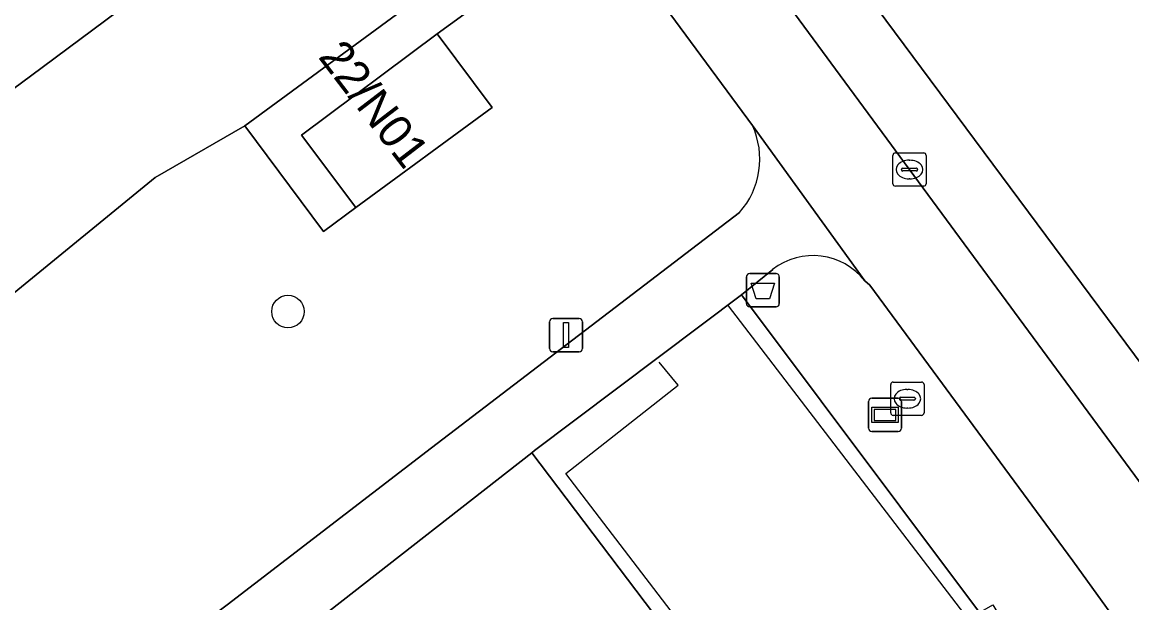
# Model space of a CAD drawing. Extents: x 163426 to 164192, y 380329 to 381641.
# Drawn here: x 163863.26 to 163896.61, y 381091.39 to 381108.84 of the extents above; entities that cross this region are included whole.
import ezdxf

# ---------------------------------------------------------------- set-up
doc = ezdxf.new("R2010")
doc.units = 0
for name, color, linetype in [('IMGEO_Afvalbak', 7, 'Continuous'), ('IMGEO_Boom', 7, 'Continuous'), ('IMGEO_Brandkraan', 7, 'Continuous'), ('IMGEO_Erf', 7, 'Continuous'), ('IMGEO_Fietspad_open', 7, 'Continuous'), ('IMGEO_Groenvoorziening', 7, 'Continuous'), ('IMGEO_Hek', 7, 'Continuous'), ('IMGEO_Kolk', 7, 'Continuous'), ('IMGEO_Lichtmast', 7, 'Continuous'), ('IMGEO_Pand', 7, 'Continuous'), ('IMGEO_Pand_nummerreeks', 7, 'Continuous'), ('IMGEO_Verklikker', 7, 'Continuous'), ('IMGEO_Voetpad_halfverhard', 7, 'Continuous'), ('IMGEO_Voetpad_open', 7, 'Continuous')]:
    doc.layers.add(name, color=color, linetype=linetype)

msp = doc.modelspace()

# ---------------------------------------------------------------- linework, layer by layer
at = {"layer": 'IMGEO_Afvalbak'}
for p, q in [((163885.023, 381100.383), (163885.023, 381101.183)), ((163885.023, 381101.183), (163885.023, 381100.383)), ((163885.123, 381101.283), (163885.913, 381101.283)), ((163885.913, 381101.283), (163885.123, 381101.283)), ((163886.013, 381101.183), (163886.013, 381100.383)), ((163886.013, 381100.383), (163886.013, 381101.183)), ((163885.913, 381100.283), (163885.123, 381100.283)), ((163885.123, 381100.283), (163885.913, 381100.283))]:
    msp.add_line(p, q, dxfattribs=at)
msp.add_lwpolyline([(163885.166, 381100.997), (163885.87, 381100.997), (163885.721, 381100.527), (163885.315, 381100.527), (163885.166, 381100.997)], dxfattribs=at)
for centre, start, end in [((163885.123, 381101.183), 90, 180), ((163885.123, 381101.183), 90, 180), ((163885.913, 381101.183), 0, 90), ((163885.913, 381101.183), 360, 90), ((163885.123, 381100.383), 180, 270), ((163885.123, 381100.383), 180, 270), ((163885.913, 381100.383), 270, 0), ((163885.913, 381100.383), 270, 0)]:
    msp.add_arc(centre, 0.1, start, end, dxfattribs=at)
at = {"layer": 'IMGEO_Boom'}
msp.add_circle((163871.246, 381100.142), 0.489, dxfattribs=at)
at = {"layer": 'IMGEO_Brandkraan'}
for p, q in [((163889.361, 381097.097), (163889.361, 381097.949)), ((163889.436, 381098.023), (163890.288, 381098.023)), ((163889.849, 381097.803), (163889.874, 381097.803)), ((163890.362, 381097.949), (163890.362, 381097.097)), ((163889.62, 381097.517), (163889.62, 381097.529)), ((163890.058, 381097.48), (163889.66, 381097.48)), ((163889.663, 381097.566), (163890.061, 381097.566)), ((163890.104, 381097.529), (163890.104, 381097.517)), ((163889.872, 381097.243), (163889.847, 381097.243)), ((163890.288, 381097.023), (163889.436, 381097.023))]:
    msp.add_line(p, q, dxfattribs=at)
for points in [[(163889.361, 381097.097), (163889.361, 381097.949)], [(163889.436, 381098.023), (163890.288, 381098.023)], [(163890.362, 381097.949), (163890.362, 381097.097)], [(163890.288, 381097.023), (163889.436, 381097.023)]]:
    msp.add_lwpolyline(points, dxfattribs=at)
for centre, radius, start, end in [((163889.438, 381097.947), 0.0765, 91.552, 178.448), ((163889.438, 381097.947), 0.0765, 91.552, 178.448), ((163890.286, 381097.947), 0.0765, 1.552, 88.448), ((163890.286, 381097.947), 0.0765, 1.552, 88.448), ((163889.66, 381097.526), 0.0403, 85.8775, 175.7526), ((163889.657, 381097.516), 0.0366, 178.938, 274.7102), ((163890.061, 381097.523), 0.043, 264.8664, 352.4533), ((163890.065, 381097.528), 0.0386, 1.7309, 96.639), ((163889.438, 381097.099), 0.0765, 181.552, 268.448), ((163889.438, 381097.099), 0.0765, 181.552, 268.448), ((163890.286, 381097.099), 0.0765, 271.552, 358.448), ((163890.286, 381097.099), 0.0765, 271.552, 358.448)]:
    msp.add_arc(centre, radius, start, end, dxfattribs=at)
for centre, major_axis, ratio, start_param, end_param in [((163889.848, 381097.523), (-0.387, 0.002), 0.722429, 4.712389, 7.853982), ((163889.873, 381097.523), (-0.39, 0.002), 0.717154, 1.570796, 4.712389)]:
    msp.add_ellipse(centre, major_axis=major_axis, ratio=ratio, start_param=start_param, end_param=end_param, dxfattribs=at)
at = {"layer": 'IMGEO_Erf'}
msp.add_lwpolyline([(163882.295, 381118.226), (163898.019, 381097.05), (163899.274, 381095.308), (163900.905, 381096.518), (163902.973, 381093.731), (163901.342, 381092.521), (163917.592, 381070.453), (163952.531, 381076.448), (163942.036, 381199.692)], dxfattribs=at)
at = {"layer": 'IMGEO_Fietspad_open'}
for points in [[(163920.063, 381063.521), (163916.003, 381069.011), (163879.294, 381118.846)], [(163878.091, 381115.406), (163879.855, 381113.008), (163880.581, 381112.021), (163885.203, 381105.739), (163888.584, 381101.063), (163888.737, 381100.935), (163894.831, 381092.652), (163895.849, 381091.249), (163896.67, 381090.133), (163898.402, 381087.778), (163898.929, 381087.061), (163907.808, 381074.986), (163908.685, 381073.793), (163913.644, 381067.049), (163914.985, 381065.235), (163917.772, 381061.459), (163917.806, 381061.505)]]:
    msp.add_lwpolyline(points, dxfattribs=at)
at = {"layer": 'IMGEO_Groenvoorziening'}
for points in [[(163875.27, 381115.855), (163874.338, 381115.123), (163867.872, 381110.455), (163866.166, 381109.192), (163863.855, 381107.48), (163861.136, 381105.466), (163848.379, 381095.943), (163850.493, 381094.839), (163851.753, 381095.363), (163853.983, 381093.322), (163867.256, 381104.176)], [(163867.256, 381104.176), (163869.951, 381105.722), (163879.855, 381113.008), (163878.091, 381115.406)], [(163885.203, 381105.739), (163880.581, 381112.021), (163875.725, 381108.486), (163877.378, 381106.277), (163873.284, 381103.268), (163872.309, 381102.549), (163869.951, 381105.722), (163867.256, 381104.176), (163853.983, 381093.322), (163851.753, 381095.363), (163850.493, 381094.839), (163848.379, 381095.943), (163844.187, 381092.814), (163844.683, 381091.092)], [(163860.665, 381084.431), (163863.932, 381087.182), (163869.42, 381091.331), (163875.557, 381096.043), (163881.424, 381100.523), (163884.816, 381103.12)], [(163885.813, 381101.41), (163884.881, 381100.649), (163892.032, 381091.103), (163892.433, 381091.325), (163893.363, 381089.769), (163893.712, 381086.589), (163885.188, 381079.149), (163877.401, 381069.894), (163877.35, 381068.327), (163876.539, 381066.473), (163872.253, 381063.156), (163871.244, 381061.59), (163871.684, 381058.886), (163871, 381056.23), (163869.868, 381054.37), (163867.112, 381051.126), (163865.984, 381046.133)], [(163873.767, 381061.119), (163873.306, 381061.714), (163874.824, 381062.84), (163881.373, 381067.697), (163879.447, 381070.311), (163879.387, 381070.393), (163879.593, 381070.547), (163883.835, 381073.718), (163883.575, 381074.205), (163883.054, 381074.889), (163887.858, 381079.918), (163898.402, 381087.778), (163896.67, 381090.133), (163895.849, 381091.249), (163894.831, 381092.652), (163888.737, 381100.935), (163888.584, 381101.063)], [(163859.052, 381037.328), (163858.039, 381032.201), (163856.309, 381029.254), (163852.062, 381030.665), (163857.097, 381046.206), (163865.555, 381060.95), (163867.201, 381064.226), (163858.767, 381069.713), (163869.611, 381086.378), (163878.149, 381080.823), (163885.102, 381087.269), (163878.573, 381095.902), (163872.498, 381091.145), (163864.015, 381084.713)]]:
    msp.add_lwpolyline(points, dxfattribs=at)
msp.add_lwpolyline([(163884.881, 381100.649), (163878.655, 381095.966), (163878.573, 381095.902), (163885.102, 381087.269), (163885.54, 381087.511), (163891.682, 381090.91), (163892.032, 381091.103)], close=True, dxfattribs=at)
for centre, radius, start, end in [((163883.009, 381104.725), 2.417, 318.3836, 24.8053), ((163887.024, 381099.846), 1.978, 37.9623, 127.7622)]:
    msp.add_arc(centre, radius, start, end, dxfattribs=at)
at = {"layer": 'IMGEO_Hek'}
for points in [[(163884.476, 381100.317), (163891.682, 381090.91)], [(163885.54, 381087.511), (163879.594, 381095.281), (163882.973, 381097.928), (163882.403, 381098.624)]]:
    msp.add_lwpolyline(points, dxfattribs=at)
at = {"layer": 'IMGEO_Kolk'}
for p, q in [((163889.425, 381103.985), (163889.425, 381104.837)), ((163889.5, 381104.911), (163890.352, 381104.911)), ((163890.426, 381104.837), (163890.426, 381103.985)), ((163889.727, 381104.454), (163890.125, 381104.454)), ((163889.913, 381104.691), (163889.938, 381104.691)), ((163889.684, 381104.405), (163889.684, 381104.417)), ((163890.122, 381104.368), (163889.724, 381104.368)), ((163889.936, 381104.131), (163889.911, 381104.131)), ((163890.168, 381104.417), (163890.168, 381104.405)), ((163890.352, 381103.911), (163889.5, 381103.911))]:
    msp.add_line(p, q, dxfattribs=at)
for points in [[(163889.425, 381103.985), (163889.425, 381104.837)], [(163889.5, 381104.911), (163890.352, 381104.911)], [(163890.426, 381104.837), (163890.426, 381103.985)], [(163890.352, 381103.911), (163889.5, 381103.911)]]:
    msp.add_lwpolyline(points, dxfattribs=at)
for centre, radius, start, end in [((163889.502, 381104.835), 0.0765, 91.552, 178.448), ((163889.502, 381104.835), 0.0765, 91.552, 178.448), ((163890.35, 381104.835), 0.0765, 1.552, 88.448), ((163890.35, 381104.835), 0.0765, 1.552, 88.448), ((163889.724, 381104.414), 0.0403, 85.8775, 175.7526), ((163890.129, 381104.416), 0.0386, 1.7309, 96.639), ((163889.721, 381104.404), 0.0366, 178.938, 274.7102), ((163890.125, 381104.411), 0.043, 264.8664, 352.4533), ((163889.502, 381103.987), 0.0765, 181.552, 268.448), ((163889.502, 381103.987), 0.0765, 181.552, 268.448), ((163890.35, 381103.987), 0.0765, 271.552, 358.448), ((163890.35, 381103.987), 0.0765, 271.552, 358.448)]:
    msp.add_arc(centre, radius, start, end, dxfattribs=at)
for centre, major_axis, ratio, start_param, end_param in [((163889.912, 381104.411), (-0.387, 0.002), 0.722429, 4.712389, 7.853982), ((163889.937, 381104.411), (-0.39, 0.002), 0.717154, 1.570796, 4.712389)]:
    msp.add_ellipse(centre, major_axis=major_axis, ratio=ratio, start_param=start_param, end_param=end_param, dxfattribs=at)
at = {"layer": 'IMGEO_Lichtmast'}
for p, q in [((163879.105, 381099.036), (163879.105, 381099.836)), ((163879.105, 381099.836), (163879.105, 381099.036)), ((163879.205, 381099.936), (163879.995, 381099.936)), ((163879.995, 381099.936), (163879.205, 381099.936)), ((163880.095, 381099.836), (163880.095, 381099.036)), ((163880.095, 381099.036), (163880.095, 381099.836)), ((163879.995, 381098.936), (163879.205, 381098.936)), ((163879.205, 381098.936), (163879.995, 381098.936))]:
    msp.add_line(p, q, dxfattribs=at)
msp.add_lwpolyline([(163879.525, 381099.811), (163879.675, 381099.811), (163879.675, 381099.061), (163879.525, 381099.061), (163879.525, 381099.811)], dxfattribs=at)
for centre, start, end in [((163879.205, 381099.836), 90, 180), ((163879.205, 381099.836), 90, 180), ((163879.995, 381099.836), 0, 90), ((163879.995, 381099.836), 360, 90), ((163879.205, 381099.036), 180, 270), ((163879.205, 381099.036), 180, 270), ((163879.995, 381099.036), 270, 0), ((163879.995, 381099.036), 270, 0)]:
    msp.add_arc(centre, 0.1, start, end, dxfattribs=at)
at = {"layer": 'IMGEO_Pand'}
for points in [[(163865.949, 381113.043), (163869.523, 381115.699), (163868.22, 381117.481), (163868.755, 381117.872), (163866.401, 381121.058), (163857.795, 381114.702), (163859.858, 381111.91), (163857.605, 381110.245), (163861.136, 381105.466), (163863.855, 381107.48), (163866.166, 381109.192), (163864.245, 381111.777)], [(163873.284, 381103.268), (163877.378, 381106.277), (163875.725, 381108.486), (163871.655, 381105.448)]]:
    msp.add_lwpolyline(points, close=True, dxfattribs=at)
at = {"layer": 'IMGEO_Verklikker'}
for p, q in [((163888.794, 381097.537), (163889.584, 381097.537)), ((163889.584, 381097.537), (163888.794, 381097.537)), ((163888.694, 381096.637), (163888.694, 381097.437)), ((163888.694, 381097.437), (163888.694, 381096.637)), ((163889.684, 381097.437), (163889.684, 381096.637)), ((163889.684, 381096.637), (163889.684, 381097.437)), ((163889.584, 381096.537), (163888.794, 381096.537)), ((163888.794, 381096.537), (163889.584, 381096.537))]:
    msp.add_line(p, q, dxfattribs=at)
for points in [[(163888.795, 381097.269), (163889.583, 381097.269), (163889.583, 381096.805), (163888.795, 381096.805), (163888.795, 381097.269)], [(163888.86, 381097.204), (163888.86, 381096.87), (163889.518, 381096.87), (163889.518, 381097.204), (163888.86, 381097.204)]]:
    msp.add_lwpolyline(points, dxfattribs=at)
for centre, start, end in [((163888.794, 381097.437), 90, 180), ((163888.794, 381097.437), 90, 180), ((163889.584, 381097.437), 0, 90), ((163889.584, 381097.437), 360, 90), ((163888.794, 381096.637), 180, 270), ((163888.794, 381096.637), 180, 270), ((163889.584, 381096.637), 270, 0), ((163889.584, 381096.637), 270, 0)]:
    msp.add_arc(centre, 0.1, start, end, dxfattribs=at)
at = {"layer": 'IMGEO_Voetpad_halfverhard'}
for points in [[(163888.584, 381101.063), (163885.203, 381105.739)], [(163884.816, 381103.12), (163881.424, 381100.523), (163875.557, 381096.043), (163869.42, 381091.331), (163863.932, 381087.182), (163860.665, 381084.431)], [(163864.015, 381084.713), (163872.498, 381091.145), (163878.573, 381095.902), (163878.655, 381095.966), (163884.881, 381100.649), (163885.813, 381101.41)]]:
    msp.add_lwpolyline(points, dxfattribs=at)
for centre, radius, start, end in [((163883.009, 381104.725), 2.417, 318.3836, 24.8053), ((163887.024, 381099.846), 1.978, 37.9623, 127.7622)]:
    msp.add_arc(centre, radius, start, end, dxfattribs=at)
at = {"layer": 'IMGEO_Voetpad_open'}
for points in [[(163882.189, 381120.998), (163879.294, 381118.846), (163916.003, 381069.011), (163920.063, 381063.521)], [(163952.882, 381069.081), (163952.994, 381069.1), (163954.955, 381069.405), (163952.531, 381076.448), (163917.592, 381070.453), (163901.342, 381092.521), (163899.274, 381095.308), (163898.019, 381097.05), (163882.295, 381118.226)]]:
    msp.add_lwpolyline(points, dxfattribs=at)
msp.add_lwpolyline([(163872.309, 381102.549), (163873.284, 381103.268), (163871.655, 381105.448), (163875.725, 381108.486), (163880.581, 381112.021), (163879.855, 381113.008), (163869.951, 381105.722)], close=True, dxfattribs=at)

# ---------------------------------------------------------------- texts
at = {"layer": 'IMGEO_Pand_nummerreeks'}
msp.add_text('22/N01', height=1, rotation=307.4506, dxfattribs=at).set_placement((163872.131, 381107.795))

doc.saveas('drawing.dxf')
